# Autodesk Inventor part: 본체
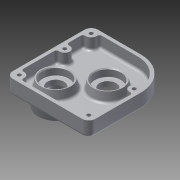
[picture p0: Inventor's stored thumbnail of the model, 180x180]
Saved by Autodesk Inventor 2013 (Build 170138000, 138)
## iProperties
Created: 2015-11
Part Number: 본체
Material: 알루미늄 6061
Document SubType Name: Modeling
Designer: Administrator
Density: 1 g/cm^3
Author: Administrator
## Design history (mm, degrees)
sketch "스케치1"
  geometry: L1 (-44.906, -34.091)-(39.094, -34.091); L2 (47.094, -26.091)-(47.094, 28.909); L3 (7.094, 68.909)-(-44.906, 68.909); L4 (-52.906, 60.909)-(-52.906, -26.091); A1 r 40 centre (7.094, 28.909) between (47.094, 28.909) and (7.094, 68.909); A2 r 8 centre (-44.906, 60.909) between (-44.906, 68.909) and (-52.906, 60.909); A3 r 8 centre (-44.906, -26.091) between (-52.906, -26.091) and (-44.906, -34.091); A4 r 8 centre (39.094, -26.091) between (39.094, -34.091) and (47.094, -26.091); 4 further points
  constraints: 8 end point, 8 point on circle, 8 tangent, 6 point on line, 4 centre point, 2 equal radius, 2 parallel, 1 horizontal, 1 perpendicular
  dimensions: "d0" = 103 distance of point (-52.906, 68.909) point (-52.906, -34.091); "d2" = 100 distance of point (-52.906, -34.091) point (47.094, -34.091); "d3" = 40 radius of A1; "d4" = 8 radius of A2
extrude "돌출1" new body sketch "스케치1" distance "d5" = 18; taper "d6" = 0 deg
sketch "스케치2"
  geometry: L1 (47.094, -26.091)-(47.094, 28.909) reference; L2 (7.094, 68.909)-(-44.906, 68.909) reference; L3 (-52.906, 60.909)-(-52.906, -26.091) reference; L4 (-44.906, -34.091)-(39.094, -34.091) reference; A1 r 40 centre (7.094, 28.909) between (47.094, 28.909) and (7.094, 68.909) reference; A2 r 8 centre (-44.906, 60.909) between (-44.906, 68.909) and (-52.906, 60.909) reference; A3 r 8 centre (-44.906, -26.091) between (-52.906, -26.091) and (-44.906, -34.091) reference; A4 r 8 centre (39.094, -26.091) between (39.094, -34.091) and (47.094, -26.091) reference; 1 further point
feature "쉘1" dims "d9" = 4
sketch "스케치3"
  geometry: L1 (88, 4)-(88, 59) reference; L2 (52, 95)-(0, 95) reference; L3 (-4, 91)-(-4, 4) reference; L4 (0, 0)-(84, 0) reference; L5 (84, -4)-(0, -4) reference; L6 (-8, 4)-(-8, 91) reference; L7 (0, 99)-(52, 99) reference; L8 (92, 59)-(92, 4) reference; L9 (0, 59)-(84, 59); C1 r 6 at (0, 91); C2 r 6 at (0, 4); C3 r 6 at (0, 59); C4 r 6 at (84, 59); C5 r 6 at (84, 4); A1 r 4 centre (0, 91) between (0, 95) and (-4, 91) reference; A2 r 4 centre (0, 4) between (-4, 4) and (0, 0) reference; A3 r 4 centre (84, 4) between (84, 0) and (88, 4) reference; A4 r 36 centre (52, 59) between (88, 59) and (52, 95) reference; A5 r 4 centre (0, 91) between (0, 95) and (-4, 91) reference; A6 r 4 centre (0, 4) between (-4, 4) and (0, 0) reference; A7 r 8 centre (84, 4) between (84, -4) and (92, 4) reference; A8 r 8 centre (0, 4) between (-8, 4) and (0, -4) reference; A9 r 8 centre (0, 91) between (0, 99) and (-8, 91) reference; A10 r 40 centre (52, 59) between (92, 59) and (52, 99) reference; 1 further point
  constraints: 5 centre point, 4 coincident, 2 end point, 1 perpendicular
  dimensions: "d10" = 12 diameter of C1; "d12" = 6 radius of C2; "d14" = 6 radius of C3; "d15" = 84 distance of L9.start L9.end; "d16" = 6 radius of C4; "d17" = 6 radius of C5
extrude "돌출2" join sketch "스케치3" distance "d18" = 14; taper "d19" = 0 deg
fillet "모깎기2" dims "d21" = 3
fillet "모깎기3" dims "d22" = 3
sketch "스케치4"
  geometry: L1 (0, 89)-(43.056, 89) reference; L2 (-9.944, 64.944)-(-9.944, 79.056) reference; L3 (-9.944, 9.944)-(-9.944, 47.056) reference; L4 (66.111, 0)-(0, 0) reference; L5 (76.056, 47.056)-(76.056, 9.944) reference; A1 r 33 centre (43.056, 56) between (74.806, 64.997) and (43.056, 89) reference; A2 r 9 centre (-8.944, 88) between (-9.944, 79.056) and (0, 89) reference; A3 r 9 centre (-8.944, 56) between (-9.944, 47.056) and (-9.944, 64.944) reference; A4 r 9 centre (-8.944, 1) between (0, 0) and (-9.944, 9.944) reference; A5 r 9 centre (75.056, 1) between (76.056, 9.944) and (66.111, 0) reference; A6 r 9 centre (75.056, 56) between (74.806, 64.997) and (76.056, 47.056) reference; 1 further point
sketch "스케치5"
  geometry: L1 (0, 89)-(43.056, 89) reference; L2 (-9.944, 64.944)-(-9.944, 79.056) reference; L3 (-9.944, 9.944)-(-9.944, 47.056) reference; L4 (66.111, 0)-(0, 0) reference; L5 (76.056, 47.056)-(76.056, 9.944) reference; A1 r 33 centre (43.056, 56) between (74.806, 64.997) and (43.056, 89) reference; A2 r 9 centre (-8.944, 88) between (-9.944, 79.056) and (0, 89) reference; A3 r 9 centre (-8.944, 56) between (-9.944, 47.056) and (-9.944, 64.944) reference; A4 r 9 centre (-8.944, 1) between (0, 0) and (-9.944, 9.944) reference; A5 r 9 centre (75.056, 1) between (76.056, 9.944) and (66.111, 0) reference; A6 r 9 centre (75.056, 56) between (74.806, 64.997) and (76.056, 47.056) reference; 1 further point
sketch "스케치6"
  geometry: A1 r 6 centre (-44.906, -26.091) between (-38.943, -26.758) and (-45.573, -20.128) reference; A2 r 6 centre (-44.906, 28.909) between (-45.573, 22.946) and (-45.573, 34.872) reference; A3 r 6 centre (39.094, 28.909) between (38.927, 34.906) and (39.761, 22.946) reference; A4 r 8 centre (-44.906, 60.909) between (-44.906, 68.909) and (-52.906, 60.909) reference; A5 r 8 centre (39.094, -26.091) between (39.094, -34.091) and (47.094, -26.091) reference; 1 further point
hole "구멍1" sketch "스케치6" at (-44.906, 60.909), (-44.906, 28.909), (39.094, 28.909), (39.094, -26.091), (-44.906, -26.091) diameter "d23" = 4.5; stored, may be unused: countersink angle "d27" = 90 deg, drill point angle "d29" = 118 deg; dims "d24" = 6, "d25" = 4, "d26" = 2, "d28" = 8
sketch "스케치7"
  geometry: C1 r 2.25 at (-39.094, -26.091) reference; C2 r 2.25 at (44.906, 28.909) reference; C3 r 2.25 at (44.906, 60.909) reference; C4 r 2.25 at (-39.094, 28.909) reference; C5 r 2.25 at (44.906, -26.091) reference; 1 further point
hole "구멍2" sketch "스케치7" at (-39.094, 28.909), (-39.094, -26.091), (44.906, -26.091), (44.906, 28.909), (44.906, 60.909) diameter "d30" = 4.5; stored, may be unused: countersink angle "d34" = 90 deg, drill point angle "d36" = 118 deg; dims "d31" = 6, "d32" = 8, "d33" = 4.4, "d35" = 17
sketch "스케치8"
  geometry: L1 (-16.944, 88)-(-16.944, 1) reference; L2 (-8.944, -7)-(75.056, -7) reference; L3 (-16.944, 1)-(-16.944, -7); L4 (-9.944, -7)-(-16.944, -7); L5 (-16.944, -7)-(13.056, -7); L6 (13.056, -7)-(13.056, 23); L7 (13.056, 23)-(-16.944, 23); L8 (-16.944, 23)-(-16.944, -7); L9 (-16.944, -7)-(46.056, -7); L10 (46.056, -7)-(46.056, 53); L11 (46.056, 53)-(-16.944, 53); L12 (-16.944, 53)-(-16.944, -7); C1 r 20 at (13.056, 23); C2 r 20 at (46.056, 53); 1 further point
  constraints: 20 end point, 4 parallel, 4 perpendicular, 2 centre point, 2 coincident, 2 horizontal
  dimensions: "d37" = 30 distance of L7.end L6.end; "d38" = 30 distance of L6.end L5.end; "d40" = 20 radius of C1; "d41" = 63 distance of L11.end L10.end; "d42" = 60 distance of L10.end L9.end; "d43" = 20 radius of C2
extrude "돌출3" join sketch "스케치8" distance "d44" = 11; taper "d45" = -10 deg
fillet "모깎기4" dims "d46" = 3
sketch "스케치9"
  geometry: C1 r 18.06 at (0, 0) reference; 1 further point
hole "구멍3" sketch "스케치9" at (0, 0) diameter "d47" = 20; stored, may be unused: countersink angle "d51" = 90 deg, drill point angle "d53" = 118 deg; dims "d48" = 6, "d49" = 32, "d50" = 9, "d52" = 50
sketch "스케치10"
  geometry: C1 r 18.06 at (0, 0) reference; 1 further point
hole "구멍4" sketch "스케치10" at (0, 0) diameter "d54" = 20; stored, may be unused: countersink angle "d58" = 90 deg, drill point angle "d60" = 118 deg; dims "d55" = 6, "d56" = 32, "d57" = 9, "d59" = 50
chamfer "모따기1" distance "d61" = 1; stored, may be unused: second distance "d62" = 2, angle "d63" = 45 deg
fillet "모깎기5" dims "d64" = 0.3
sketch "스케치11"
  geometry: C1 r 10 at (22.906, -4.091) reference; C2 r 25 at (22.906, -2.936); 1 further point
  constraints: 1 centre point
  dimensions: "d65" = 25 radius of C2
extrude "돌출4" join sketch "스케치11" distance "d66" = 15; taper "d67" = -10 deg
sketch "스케치12"
  geometry: C1 r 12.645 at (0, -1.155) reference; C2 r 14 at (0, -1.155); 1 further point
  constraints: 1 centre point, 1 coincident
  dimensions: "d68" = 14 radius of C2
extrude "돌출5" cut sketch "스케치12" distance "d70" = 11; taper "d71" = 0 deg
chamfer "모따기2" distance "d72" = 1; stored, may be unused: second distance "d73" = 2, angle "d74" = 45 deg
sketch "스케치13"
  geometry: C1 r 10.705 at (0, 0) reference; C2 r 14 at (0, 0) reference; C3 r 12 at (0, 0); 1 further point
  constraints: 1 centre point, 1 coincident
  dimensions: "d75" = 24 diameter of C3
extrude "돌출6" cut sketch "스케치13" distance "d76" = 2; taper "d77" = 0 deg
fillet "모깎기6" dims "d78" = 2
fillet "모깎기7" dims "d79" = 0.3
sketch "스케치14" dims "d80" = 36
  geometry: C1 r 15 at (0, -1.155) reference; 3 further points
  constraints: 1 coincident, 1 vertical alignment, 2 other
hole "구멍5" sketch "스케치14" at (0, 16.845) diameter "d81" = 2.459; stored, may be unused: countersink angle "d85" = 90 deg, drill point angle "d87" = 118 deg; dims "d82" = 8, "d83" = 28, "d84" = 11, "d86" = 10
sketch "스케치15"
  geometry: L1 (52.906, -26.091)-(52.906, 60.909) reference; L2 (44.906, 68.909)-(-7.094, 68.909) reference; 2 further points
  constraints: 1 other
  dimensions: "d91" = 40 distance from line of L1 point (12.906, 48.909); "d92" = 20 distance from line of point (12.906, 48.909) L2
feature "엠보싱1" sketch "스케치15" dims "d0" = 103, "d2" = 100, "d3" = 40, "d4" = 8, "d93" = 0.5, "d94" = 0
fillet "모깎기8" dims "d95" = 3
fillet "모깎기9" dims "d96" = 3
node "솔리드1"
pattern_circular "원형 패턴1" dims angle "d89" = 360 deg
node "절단 모서리 투영1"
